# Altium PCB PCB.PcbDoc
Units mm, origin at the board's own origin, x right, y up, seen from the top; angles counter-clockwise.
Board outline 140 x 140 mm, 2 copper layers (TOP, BOTTOM), stack 1.586 mm thick; 2 components, 1 nets, 53 pads, 0 vias.
Unrouted connection lines stored in the file: 1.
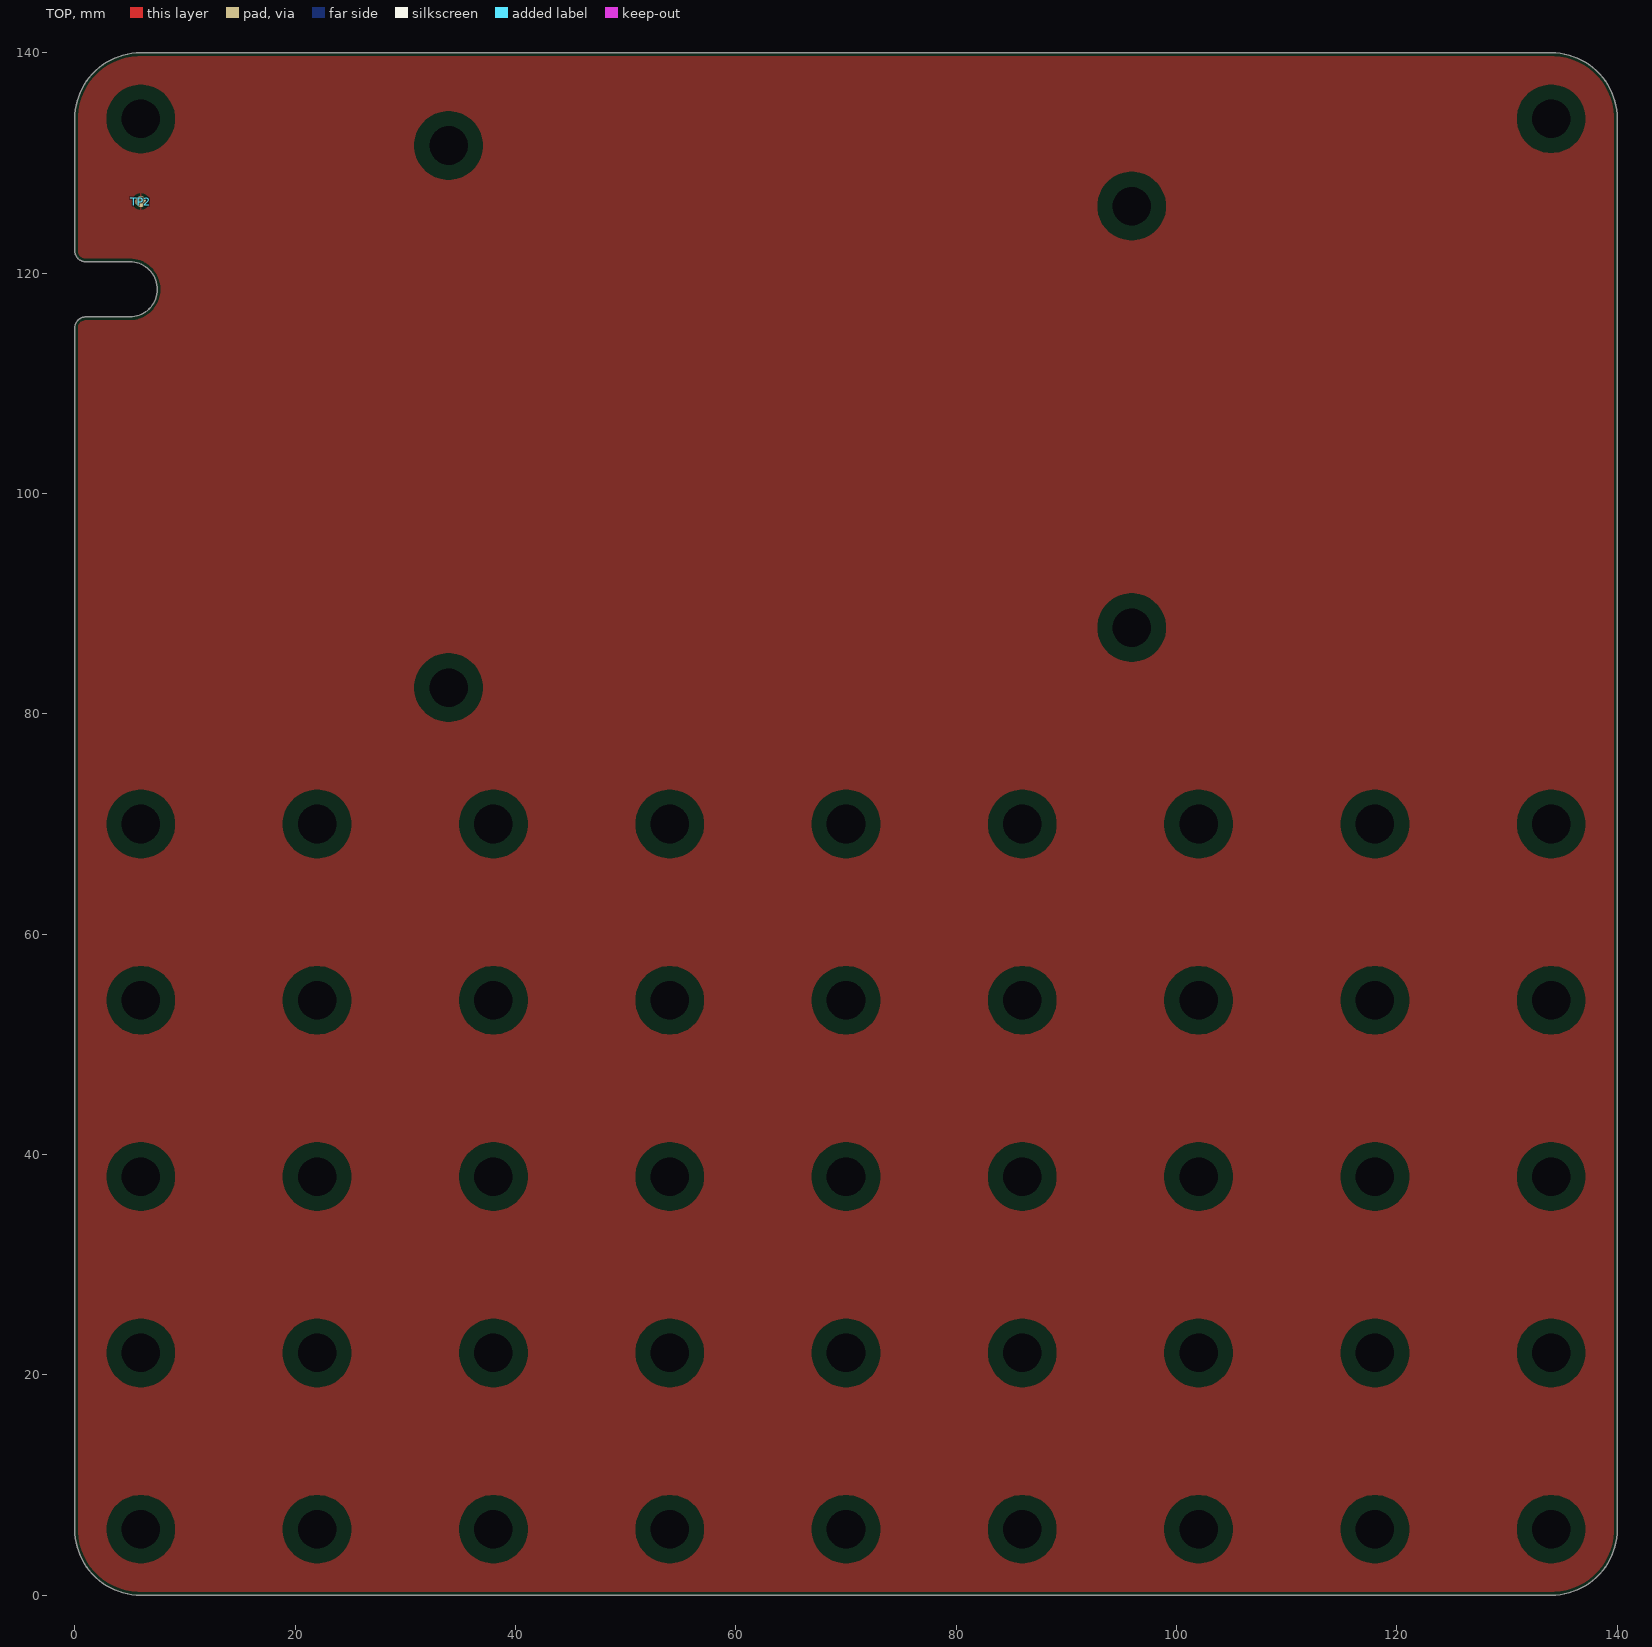
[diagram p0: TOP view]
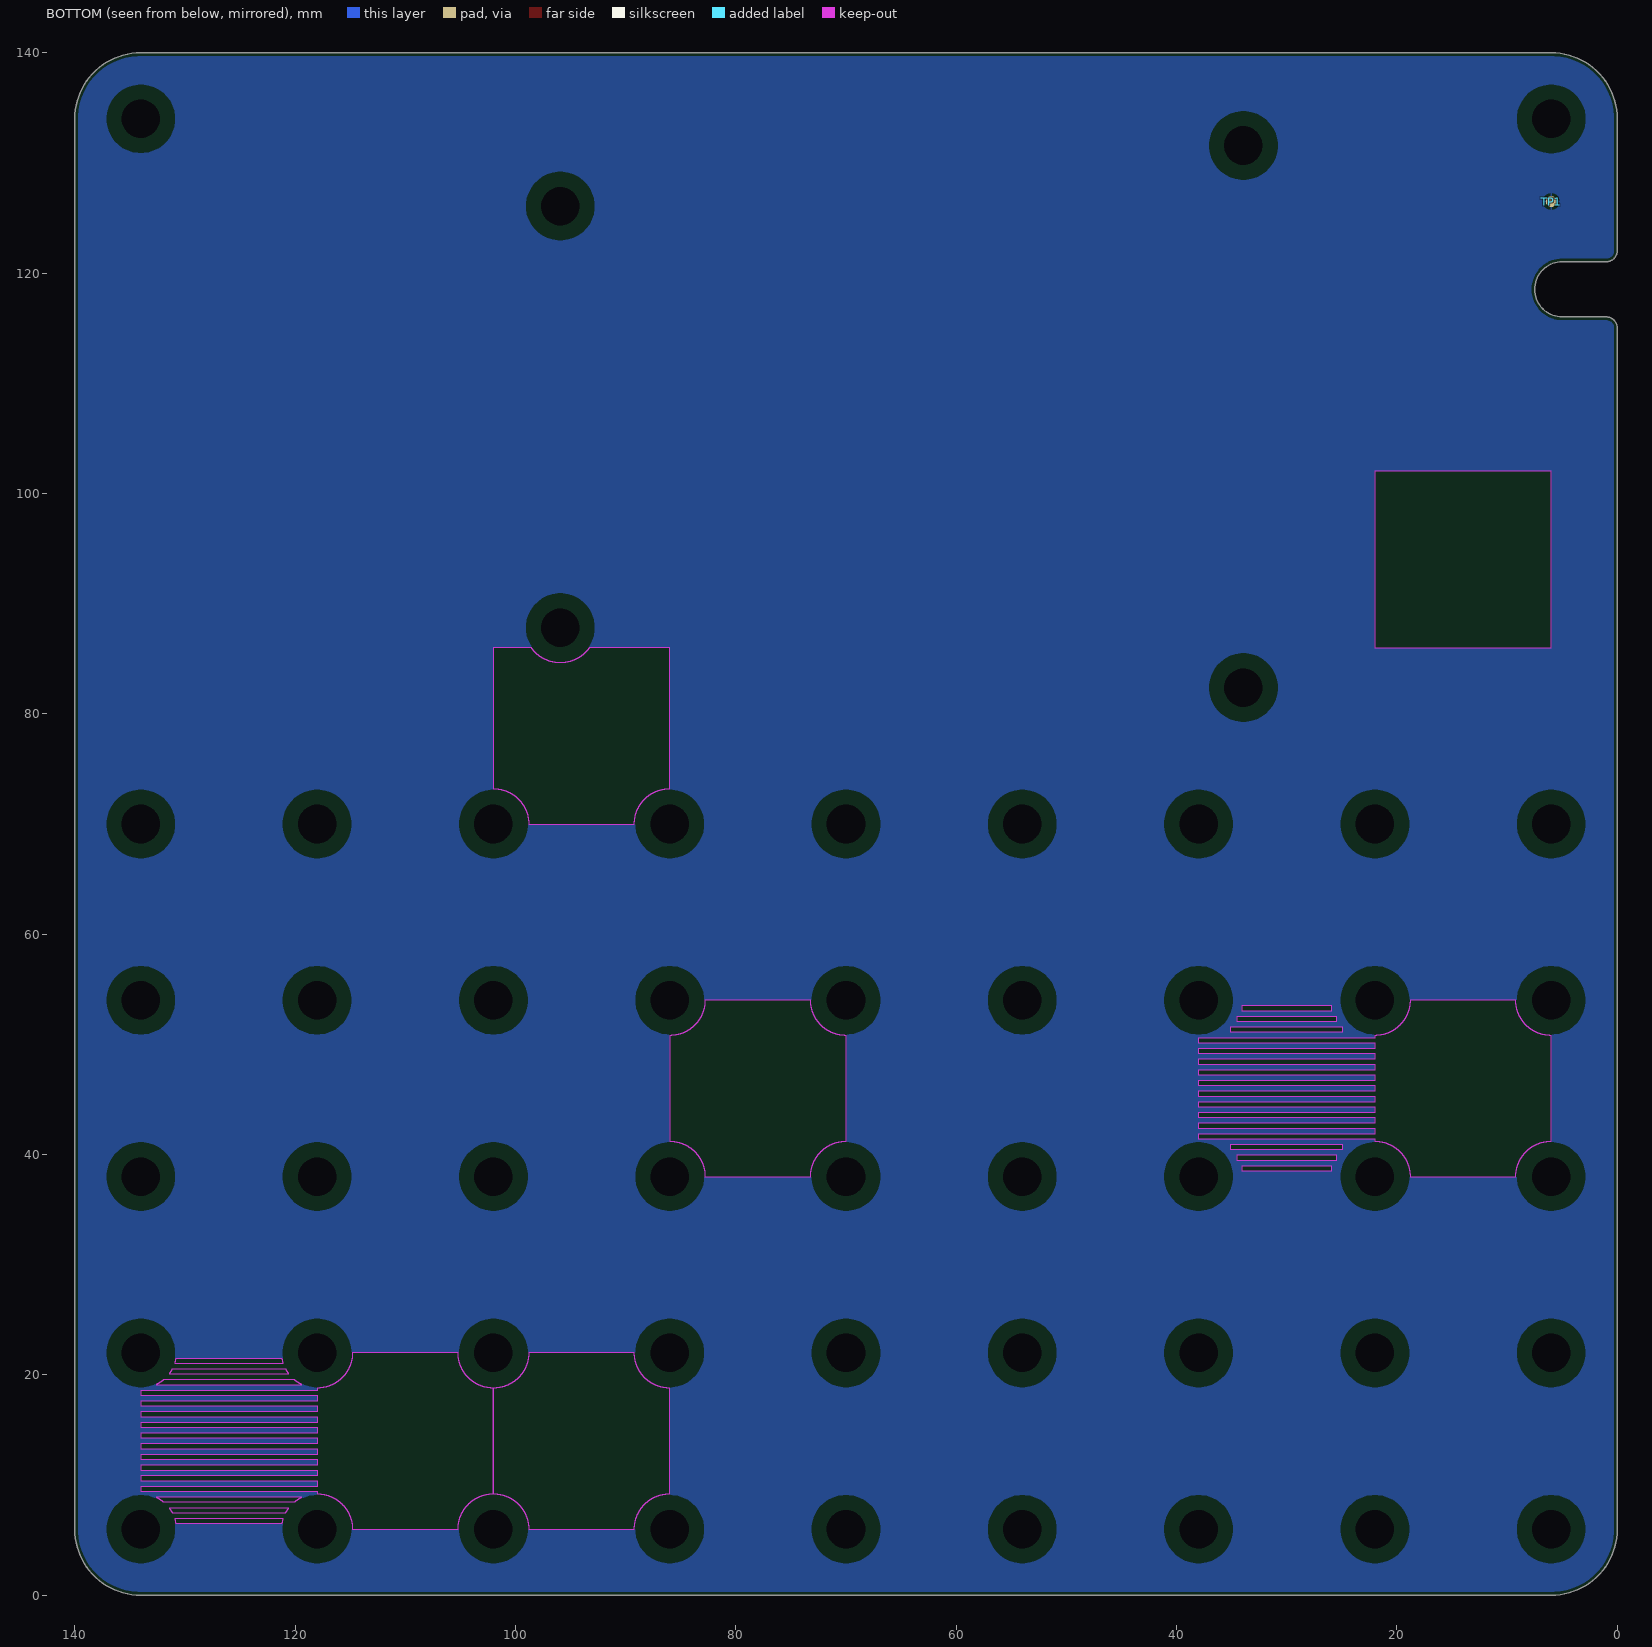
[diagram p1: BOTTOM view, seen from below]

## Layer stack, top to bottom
Top Solder: solder mask 0.01, Solder Resist, Dk 3.5
TOP: signal copper 0.018
Dielectric: core 1.55, FR-4, Dk 4.8
BOTTOM: signal copper 0.018
Bottom Solder: solder mask 0.01, Solder Resist, Dk 3.5

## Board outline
6,0 cw(c6,6) 0,6 0,115.024 cw(c1,115.024) 1,116.024 5,116.024 ccw(c5,118.524) 5,121.024 1,121.024 cw(c1,122.024) 0,122.024 0,134 cw(c6,134) 6,140 134,140 cw(c134,134) 140,134 140,6 cw(c134,6) 134,0

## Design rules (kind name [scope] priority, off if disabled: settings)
BoardOutlineClearance Mousebites [(ObjectKind = 'Pad') And (Name = 'Free-MOUSEBITE')] p1: gap=0 ignorepadtopadclearanceinfootprint=FALSE
BoardOutlineClearance Silks [(OnLayer('Top Overlay') OR OnLayer('Bottom Overlay'))] p2: gap=0 ignorepadtopadclearanceinfootprint=FALSE
BoardOutlineClearance [All] p3: gap=0.3 ignorepadtopadclearanceinfootprint=FALSE
Clearance Copper_MH [All vs (ObjectKind = 'Pad') And (Name = 'Free-MH')] p1: gap=1.35 ignorepadtopadclearanceinfootprint=FALSE
Clearance Copper_ITALIA [All vs (ObjectKind = 'Region') And (Net = 'No Net') And (Area = '6.151 sq.') OR (Area = '0.625 sq.') OR (Area = '0.545 sq.')] p2: gap=0.3 ignorepadtopadclearanceinfootprint=FALSE
Clearance COPPER_0.3mm [All] p3: gap=0.127 ignorepadtopadclearanceinfootprint=FALSE except(0: Arc-Fill Arc-Poly Arc-Region Track-Fill Track-Poly Track-Region SMDPad-Fill SMDPad-Poly SMDPad-Region THPad-Fill THPad-Poly THPad-Region Via-Fill Via-Poly Via-Region Fill-Fill Fill-Poly Fill-Region Poly-Poly Poly-Region Region-Region)
Clearance "Generic clearance 0.15mm" [All] p4: gap=0.15 ignorepadtopadclearanceinfootprint=FALSE
ComponentClearance [All] p1: gap=0.2 collisioncheckmode=3 verticalgap=0 showdistances=TRUE
DiffPairsRouting USB [InDifferentialPairClass('USB')] p1: maxlimit=0.15 minlimit=0.15 mostfreqgap=0.15 toplayer_minwidth=0.15 toplayer_maxwidth=0.21 toplayer_prefwidth=0.2 bottomlayer_minwidth=0.15 bottomlayer_maxwidth=0.21 bottomlayer_prefwidth=0.2 impedanceprofiledriven=TRUE impedanceprofileid={E6B00C31-4C8E-439C-824F-D2B2CDC26F9C} impedanceprofilevalue=90.000000 maxuncoupledlength=12.7
Height [All] p1: minheight=0 maxheight=30 prefheight=12.7
HoleSize [All] p1: absolutevalues=TRUE maxlimit=30 minlimit=0.3 maxpercent=80.000 minpercent=20.000
HoleToHoleClearance [All] p1: gap=0.25 allowstackedmicrovias=FALSE
MinimumAnnularRing [All] p1: minimumring=0.15
PlaneConnect [All] p1: pad.planeconnectstyle=Relief pad.reliefexpansion=0.508 pad.reliefentries=4 pad.reliefconductorwidth=0.254 pad.reliefairgap=0.254 via.planeconnectstyle=Direct via.reliefexpansion=0.508 via.reliefentries=4 via.reliefconductorwidth=0.254 via.reliefairgap=0.254
PolygonConnect [All] p1: thpad.connectstyle=Relief thpad.reliefconductorwidth=0.3 thpad.reliefentries=4 thpad.polygonreliefangle="90 Angle" thpad.airgapwidth=0.35 smdpad.connectstyle=Relief smdpad.reliefconductorwidth=0.2 smdpad.reliefentries=4 smdpad.polygonreliefangle="90 Angle" smdpad.airgapwidth=0.254 via.connectstyle=Direct via.reliefconductorwidth=0.254 via.reliefentries=4 via.polygonreliefangle="90 Angle" via.airgapwidth=0.254
RoomDefinition TOP [InComponentClass('TOP')] p1: confinementstyle=ConfineIn formatcopy=TRUE lockcomponents=FALSE outline 97.994,29.994 125.994,29.994 125.994,37.994 97.994,37.994
RoutingVias StandardVias [All] p1: holewidth=0.3 width=0.6 viastyle="Through Hole" minholewidth=0.3 minwidth=0.6 maxholewidth=0.3 maxwidth=0.6
SMDToCorner [All] p1: distance=39370
SilkToSilkClearance [All] p1: silktosilkclearance=0.2
SilkToSolderMaskClearance [IsPad] p1: minsilkscreentomaskgap=0.15 clearancetoexposedcopper=TRUE
SolderMaskExpansion VIAtented [IsVia] p1: expansion=0.102 istentingtop=TRUE
SolderMaskExpansion [All] p2: expansion=0.05 istentingtop=FALSE
UnConnectedPin [All] p1:
UnRoutedNet [All] p1: checkbadconnections=TRUE
ViasUnderSMD [All] p1: allowed=FALSE
Width StandardTraces [All] p1: maxlimit=5 minlimit=0.127 preferedwidth=0.15
21 further rules are at their usual default settings.

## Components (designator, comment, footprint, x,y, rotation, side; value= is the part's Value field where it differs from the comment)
TP1 "Test point 1.00mm" TP-1.00MM 5.994,126.494 r90 bottom
TP2 "Test point 1.00mm" TP-1.00MM 5.994,126.494 r90 top

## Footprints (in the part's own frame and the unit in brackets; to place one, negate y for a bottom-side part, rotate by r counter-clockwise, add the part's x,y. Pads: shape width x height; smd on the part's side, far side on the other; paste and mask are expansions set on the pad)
TP-1.00MM [mm]
  rrect100% 1x1 smd paste-2.54: X(0,0)

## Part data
TP1 TP2: library part UT0013-A.6, Manufacturer="This is not a component"

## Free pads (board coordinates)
  round 3 hole 3.5 unplated mask+1: MH(5.994,133.994) MH(6,6) MH(6,22) MH(6,38) MH(6,54) MH(6,70) MH(22,6) MH(22,22) MH(22,38) MH(22,54) MH(22,70) MH(33.93,82.378) MH(33.93,131.578) MH(38,6) MH(38,22) MH(38,38) MH(38,54) MH(38,70) MH(54,6) MH(54,22) MH(54,38) MH(54,54) MH(54,70) MH(70,6) MH(70,22) MH(70,38) MH(70,54) MH(70,70) MH(86,6) MH(86,22) MH(86,38) MH(86,54) MH(86,70) MH(95.93,87.828) MH(95.93,126.077) MH(102,6) MH(102,22) MH(102,38) MH(102,54) MH(102,70) MH(118,6) MH(118,22) MH(118,38) MH(118,54) MH(118,70) MH(134,6) MH(134,22) MH(134,38) MH(134,54) MH(134,70) MH(134,134)

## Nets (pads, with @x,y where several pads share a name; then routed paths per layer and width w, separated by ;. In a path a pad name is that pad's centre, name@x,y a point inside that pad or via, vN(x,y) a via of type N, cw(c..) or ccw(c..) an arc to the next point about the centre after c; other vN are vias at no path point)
GND: TP1.X TP2.X

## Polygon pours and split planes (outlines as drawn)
GND on TOP "GND" (solid, remove dead copper, pour order 0): 6,0 cw(c6,6) 0,6 0,115.024 cw(c1,115.024) 1,116.024 5,116.024 ccw(c5,118.524) 5,121.024 1,121.024 cw(c1,122.024) 0,122.024 0,134 cw(c6,134) 6,140 134,140 cw(c134,134) 140,134 140,6 cw(c134,6) 134,0
GND on BOTTOM "GND" (solid, remove dead copper, pour order 1): 6,0 cw(c6,6) 0,6 0,115.024 cw(c1,115.024) 1,116.024 5,116.024 ccw(c5,118.524) 5,121.024 1,121.024 cw(c1,122.024) 0,122.024 0,134 cw(c6,134) 6,140 134,140 cw(c134,134) 140,134 140,6 cw(c134,6) 134,0

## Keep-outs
BOTTOM:
  region: 1423 vertices and 0 holes, not listed, extent 85.996,6 102.008,22.012
  region: 1211 vertices and 0 holes, not listed, extent 85.996,69.995 102.008,86.007
  region: 26.849,53.062 25.928,53.062 25.928,53.486 34.087,53.486 34.087,53.062 26.859,53.062
  region: 33.315,52.089 25.473,52.089 25.473,52.512 34.542,52.512 34.542,52.089 33.325,52.089
  region: 34.775,51.549 35.114,51.549 35.114,51.126 24.901,51.126 24.901,51.549 34.765,51.549
  region: 28.912,40.458 24.901,40.458 24.901,40.881 35.114,40.881 35.114,40.458 28.923,40.458
  region: 1465 vertices and 0 holes, not listed, extent 6,38.003 38.013,54.015
  region: 31.24,39.495 25.473,39.495 25.473,39.918 34.542,39.918 34.542,39.495 31.251,39.495
  region: 27.939,38.945 34.087,38.945 34.087,38.521 25.928,38.521 25.928,38.945 27.928,38.945
  region: 163 vertices and 0 holes, not listed, extent 119.416,8.466 132.592,8.89
  region: 123.089,6.519 121.163,6.519 121.163,6.561 121.152,6.561 121.152,6.625 121.141,6.625 121.141,6.678 121.131,6.678 121.131,6.72 121.12,6.72 121.12,6.762 121.11,6.762 121.11,6.805 121.099,6.805 121.099,6.847 121.089,6.847 121.089,6.889 121.078,6.889 121.078,6.921 121.067,6.921 121.067,6.942 130.931,6.942 130.931,6.911 130.92,6.911 130.92,6.879 130.909,6.879 130.909,6.836 130.899,6.836 130.899,6.794 130.888,6.794 130.888,6.752 130.878,6.752 130.878,6.71 130.867,6.71 130.867,6.657 130.856,6.657 130.856,6.604 130.846,6.604 130.846,6.54 130.835,6.54 130.835,6.519 123.099,6.519
  region: 122.295,7.493 120.835,7.493 120.835,7.514 120.824,7.514 120.824,7.535 120.813,7.535 120.813,7.556 120.803,7.556 120.803,7.577 120.792,7.577 120.792,7.588 120.782,7.588 120.782,7.609 120.771,7.609 120.771,7.63 120.76,7.63 120.76,7.651 120.75,7.651 120.75,7.662 120.739,7.662 120.739,7.683 120.729,7.683 120.729,7.704 120.718,7.704 120.718,7.715 120.708,7.715 120.708,7.736 120.697,7.736 120.697,7.747 120.686,7.747 120.686,7.768 120.676,7.768 120.676,7.778 120.665,7.778 120.665,7.8 120.655,7.8 120.655,7.81 120.644,7.81 120.644,7.831 120.633,7.831 120.633,7.842 120.623,7.842 120.623,7.863 120.612,7.863 120.612,7.874 120.602,7.874 120.602,7.884 120.591,7.884 120.591,7.905 120.581,7.905 120.581,7.916 131.417,7.916 131.417,7.895 131.407,7.895 131.407,7.884 131.396,7.884 131.396,7.874 131.386,7.874 131.386,7.852 131.375,7.852 131.375,7.842 131.364,7.842 131.364,7.821 131.354,7.821 131.354,7.81 131.343,7.81 131.343,7.789 131.333,7.789 131.333,7.778 131.322,7.778 131.322,7.757 131.312,7.757 131.312,7.747 131.301,7.747 131.301,7.725 131.29,7.725 131.29,7.715 131.28,7.715 131.28,7.694 131.269,7.694 131.269,7.673 131.259,7.673 131.259,7.662 131.248,7.662 131.248,7.641 131.237,7.641 131.237,7.62 131.227,7.62 131.227,7.609 131.216,7.609 131.216,7.588 131.206,7.588 131.206,7.567 131.195,7.567 131.195,7.546 131.185,7.546 131.185,7.524 131.174,7.524 131.174,7.514 131.163,7.514 131.163,7.493 122.306,7.493
  region: 128.888,20.52 131.163,20.52 131.163,20.499 131.174,20.499 131.174,20.478 131.185,20.478 131.185,20.467 131.195,20.467 131.195,20.446 131.206,20.446 131.206,20.425 131.216,20.425 131.216,20.404 131.227,20.404 131.227,20.393 131.237,20.393 131.237,20.372 131.248,20.372 131.248,20.351 131.259,20.351 131.259,20.34 131.269,20.34 131.269,20.319 131.28,20.319 131.28,20.298 131.29,20.298 131.29,20.287 131.301,20.287 131.301,20.266 131.312,20.266 131.312,20.256 131.322,20.256 131.322,20.234 131.333,20.234 131.333,20.224 131.343,20.224 131.343,20.203 131.354,20.203 131.354,20.192 131.364,20.192 131.364,20.171 131.375,20.171 131.375,20.16 131.386,20.16 131.386,20.139 131.396,20.139 131.396,20.129 131.407,20.129 131.407,20.118 131.417,20.118 131.417,20.097 120.581,20.097 120.581,20.107 120.591,20.107 120.591,20.129 120.602,20.129 120.602,20.139 120.612,20.139 120.612,20.15 120.623,20.15 120.623,20.171 120.633,20.171 120.633,20.181 120.644,20.181 120.644,20.203 120.655,20.203 120.655,20.213 120.665,20.213 120.665,20.234 120.676,20.234 120.676,20.245 120.686,20.245 120.686,20.266 120.697,20.266 120.697,20.277 120.708,20.277 120.708,20.298 120.718,20.298 120.718,20.308 120.729,20.308 120.729,20.33 120.739,20.33 120.739,20.351 120.75,20.351 120.75,20.361 120.76,20.361 120.76,20.382 120.771,20.382 120.771,20.404 120.782,20.404 120.782,20.414 120.792,20.414 120.792,20.435 120.803,20.435 120.803,20.457 120.813,20.457 120.813,20.478 120.824,20.478 120.824,20.499 120.835,20.499 120.835,20.52 128.877,20.52
  region: 163 vertices and 0 holes, not listed, extent 119.416,19.123 132.581,19.546
  region: 128.899,21.483 130.835,21.483 130.835,21.473 130.846,21.473 130.846,21.409 130.856,21.409 130.856,21.356 130.867,21.356 130.867,21.303 130.878,21.303 130.878,21.261 130.888,21.261 130.888,21.219 130.899,21.219 130.899,21.176 130.909,21.176 130.909,21.134 130.92,21.134 130.92,21.102 130.931,21.102 130.931,21.06 121.067,21.06 121.067,21.092 121.078,21.092 121.078,21.123 121.089,21.123 121.089,21.166 121.099,21.166 121.099,21.208 121.11,21.208 121.11,21.25 121.12,21.25 121.12,21.293 121.131,21.293 121.131,21.335 121.141,21.335 121.141,21.388 121.152,21.388 121.152,21.451 121.163,21.451 121.163,21.483 128.888,21.483
  region: 1463 vertices and 0 holes, not listed, extent 101.997,6 134.01,22.012
  region: 21.483,85.996 6,85.996 6,102.008 22.012,102.008 22.012,85.996 21.494,85.996
  region: 1431 vertices and 0 holes, not listed, extent 69.995,38.003 86.007,54.015

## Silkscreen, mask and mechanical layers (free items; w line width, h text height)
Top Solder:
  drawing of 3 lines, arcs and shapes, not listed
Bottom Solder:
  drawing of 33 lines, arcs and shapes, not listed
Route Tool Path:
  lines w2: 35,-1 6,-1 cw(c6,6) -1,6 -1,115.024 cw(c1,115.024) 0.997,117.024 ; 35,141 6,141 ccw(c6,134) -1,134 -1,122.024 ccw(c1,122.024) 0.997,120.024 ; 39,-1 71,-1 ; 39,141 71,141 ; 75,-1 106,-1 ; 75,141 106,141 ; 110,-1 134,-1 ccw(c134,6) 141,6 141,134 ; 110,141 134,141 ; 0.997,117.024 cw(c1,115.024) 1,117.024 ; 0.997,117.024 cw(c1,116.024) 1,117.024 ; 0.997,120.024 ccw(c1,121.024) 1,120.024 ; 0.997,120.024 ccw(c1,122.024) 1,120.024 ; 1,117.024 5,117.024 ccw(c5,118.524) 6.5,118.524 ccw(c5,118.524) 5,120.024 1,120.024 ; 134,141 cw(c134,140) 134.002,141 ; 134,141 cw(c134,134) 134.002,141 ; 134.002,141 cw(c134,134) 141,134.002 ; 141,134 ccw(c134,134) 141,134.002 ; 141,134 ccw(c140,134) 141,134.002
Board:
  circle w0.1: c70,54 r1.75
  circle w0.1: c70,38 r1.75
  circle w0.1: c70,70 r1.75
  circle w0.1: c118,70 r1.75
  circle w0.1: c118,70 r1.75
  circle w0.1: c54,70 r1.75
  circle w0.1: c134,70 r1.75
  circle w0.1: c134,70 r1.75
  circle w0.1: c70,6 r1.75
  circle w0.1: c22,70 r1.75
  circle w0.1: c86,70 r1.75
  circle w0.1: c70,54 r1.75
  circle w0.1: c70,54 r1.75
  circle w0.1: c70,54 r1.75
  circle w0.1: c70,38 r1.75
  circle w0.1: c70,6 r1.75
  circle w0.1: c6,70 r1.75
  circle w0.1: c102,70 r1.75
  circle w0.1: c102,70 r1.75
  circle w0.1: c70,38 r1.75
  circle w0.1: c70,22 r1.75
  circle w0.1: c6,70 r1.75
  circle w0.1: c86,70 r1.75
  circle w0.1: c102,70 r1.75
  circle w0.1: c54,70 r1.75
  circle w0.1: c38,70 r1.75
  circle w0.1: c38,70 r1.75
  circle w0.1: c70,6 r1.75
  circle w0.1: c22,70 r1.75
  circle w0.1: c22,70 r1.75
  circle w0.1: c6,70 r1.75
  circle w0.1: c6,70 r1.75
  circle w0.1: c118,70 r1.75
  circle w0.1: c134,70 r1.75
  circle w0.1: c38,70 r1.75
  circle w0.1: c70,6 r1.75
  circle w0.1: c22,70 r1.75
  circle w0.1: c86,70 r1.75
  circle w0.1: c86,70 r1.75
  circle w0.1: c70,70 r1.75
  circle w0.1: c70,70 r1.75
  circle w0.1: c54,70 r1.75
  circle w0.1: c38,70 r1.75
  circle w0.1: c102,70 r1.75
  circle w0.1: c70,70 r1.75
  circle w0.1: c118,70 r1.75
  circle w0.1: c54,70 r1.75
  circle w0.1: c134,70 r1.75
  circle w0.1: c70,38 r1.75
  circle w0.1: c70,22 r1.75
  circle w0.1: c70,22 r1.75
  circle w0.1: c70,22 r1.75
  lines w0.1: 0,6 ccw(c6,6) 6,0 134,0 ccw(c134,6) 140,6 140,134 ccw(c134,134) 134,140 6,140 ccw(c6,134) 0,134 0,122.024 ccw(c1,122.024) 1,121.024 5,121.024 cw(c5,118.524) 5,116.024 1,116.024 ccw(c1,115.024) 0,115.024 0,6 ; 0,70 4.25,70 0,70 ; 7.75,70 20.25,70 7.75,70 ; 23.75,70 36.25,70 23.75,70 ; 39.75,70 52.25,70 39.75,70 ; 55.75,70 68.25,70 55.75,70 ; 70,0 70,4.25 70,0 ; 70,7.75 70,20.25 70,7.75 ; 70,23.749 70,36.249 70,23.749 ; 70,39.75 70,52.25 70,39.75 ; 70,55.75 70,68.25 70,55.75 ; 70,71.75 70,140 70,71.75 ; 71.75,70 84.25,70 71.75,70 ; 87.75,70 100.25,70 87.75,70 ; 103.75,70 116.25,70 103.75,70 ; 119.75,70 132.25,70 119.75,70 ; 135.75,70 140,70 135.75,70
Mechanical 25:
  drawing of 213 lines, arcs and shapes, not listed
